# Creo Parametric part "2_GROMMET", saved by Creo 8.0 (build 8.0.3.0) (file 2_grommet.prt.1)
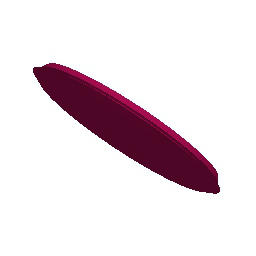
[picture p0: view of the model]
Units: millimeter Newton Second (mmNs); MM, TONNE, SECS

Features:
  1. datum plane "DTM1"
  2. protrusion
  3. datum plane "DTM3"
  4. protrusion
  5. cut

Layers: 0_ALL_AXIS, 0_ALL_CSYS, 0_ALL_CURVES, 0_ALL_PLANES, 0_ALL_POINTS, 0_ALL_SURFS, GROMMET

Surfaces: 10 cone, 3 plane, 2 cylinder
